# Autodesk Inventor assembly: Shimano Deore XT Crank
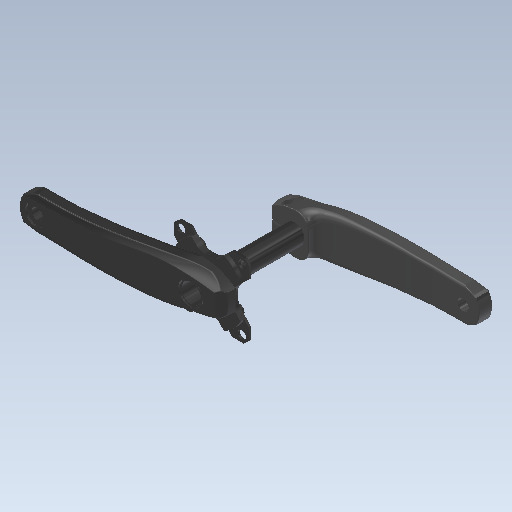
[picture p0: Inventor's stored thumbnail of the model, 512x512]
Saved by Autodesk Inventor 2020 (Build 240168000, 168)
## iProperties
Created: 2017-10
Part Number: Shimano Deore XT Crank
Material: Ogólny
Document SubType Name: Assembly
Designer: Tomasz
Sending System: SolidWorks 2017
Last Author: Tomasz
Last Saved: 2017-11-19
Author: Tomasz
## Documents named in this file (3)
- C:\Users\bruno\Documents\1-Cours-2020-21\1STI2D-2020-21\IT\6. Antivol\Inventor-Antivol\INVENTOR 2018_Steel Hardtail B+\Shimano Deore XT Crank.iam
- C:\Users\bruno\Documents\1-Cours-2020-21\1STI2D-2020-21\IT\6. Antivol\Inventor-Antivol\INVENTOR 2018_Steel Hardtail B+\DEFAULT-8.ipt
- C:\Users\bruno\Documents\1-Cours-2020-21\1STI2D-2020-21\IT\6. Antivol\Inventor-Antivol\INVENTOR 2018_Steel Hardtail B+\LEFT arm.ipt
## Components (2 placed, 2 different names)
1. DEFAULT-8:1
2. LEFT arm:1
